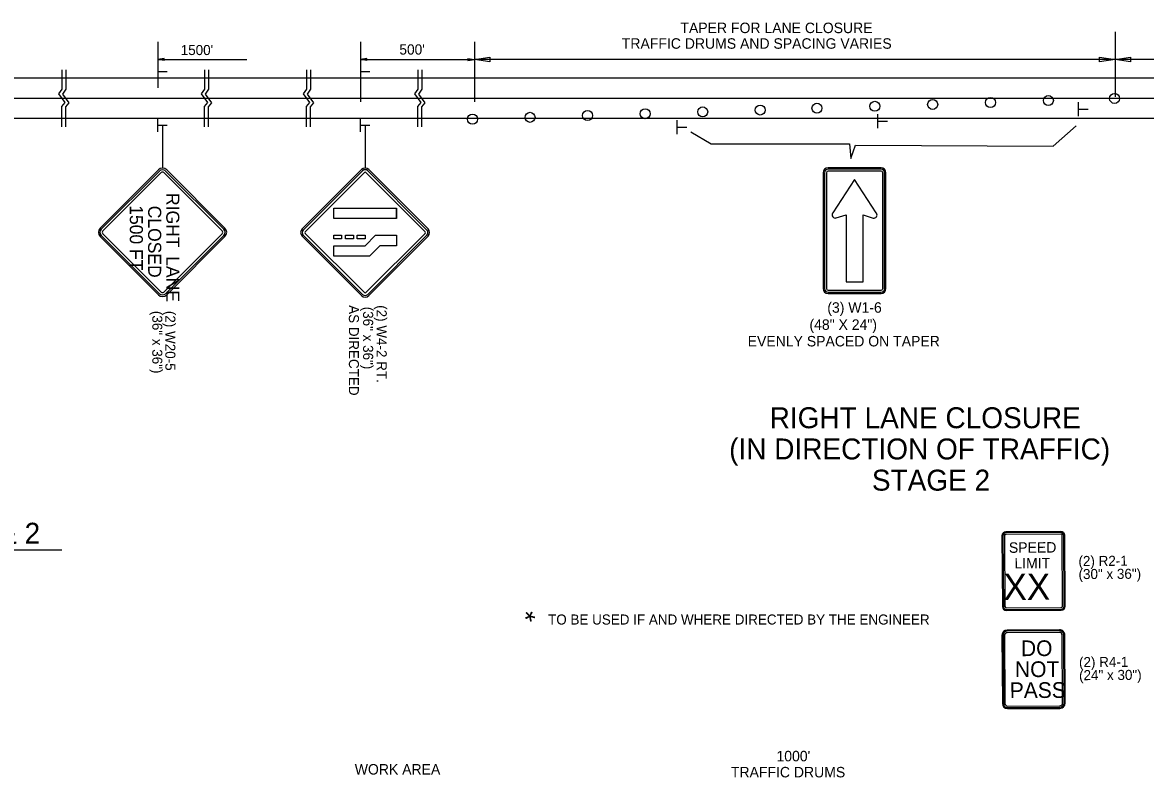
# Model space of a CAD drawing. Extents: x 1930579 to 1938745, y 596452 to 597559.
# Drawn here: x 1937136 to 1937779, y 597006 to 597439 of the extents above; entities that cross this region are included whole.
import ezdxf

# ---------------------------------------------------------------- set-up
doc = ezdxf.new("R2010")
doc.units = 0
for name, color, linetype in [('Default', 7, 'Continuous'), ('P_TC_Signs_Permanent', 7, 'Continuous'), ('P_TC_Signs_Temporary', 7, 'Continuous'), ('R_Annotation', 7, 'Continuous')]:
    doc.layers.add(name, color=color, linetype=linetype)

msp = doc.modelspace()

# ---------------------------------------------------------------- linework, layer by layer
at = {"layer": 'Default'}
for p, q in [((1937761.74, 597433.33), (1937761.74, 597396.03)), ((1937213.06, 597427.55), (1937213.06, 597401.26)), ((1937329.17, 597427.55), (1937329.17, 597393.08)), ((1937394.52, 597427.55), (1937394.52, 597393.08)), ((1937216.73, 597417.99), (1937213.06, 597417.44)), ((1937213.06, 597417.44), (1937264.16, 597417.44)), ((1937216.73, 597416.89), (1937213.06, 597417.44)), ((1937213.06, 597414.35), (1937213.06, 597406.69)), ((1937216.73, 597417.9), (1937213.67, 597417.44)), ((1937216.73, 597416.98), (1937213.67, 597417.44)), ((1937216.73, 597417.81), (1937214.3, 597417.44)), ((1937216.73, 597417.08), (1937214.3, 597417.44)), ((1937216.73, 597417.72), (1937214.91, 597417.44)), ((1937216.73, 597417.17), (1937214.91, 597417.44)), ((1937216.73, 597417.62), (1937215.54, 597417.44)), ((1937216.73, 597417.27), (1937215.54, 597417.44)), ((1937216.73, 597417.53), (1937216.15, 597417.44)), ((1937216.73, 597417.36), (1937216.15, 597417.44)), ((1937216.73, 597416.89), (1937216.73, 597417.99)), ((1937332.85, 597417.99), (1937329.17, 597417.44)), ((1937329.17, 597417.44), (1937394.52, 597417.44)), ((1937332.85, 597416.89), (1937329.17, 597417.44)), ((1937329.17, 597414.32), (1937329.17, 597406.66)), ((1937332.85, 597417.9), (1937329.79, 597417.44)), ((1937332.85, 597416.98), (1937329.79, 597417.44)), ((1937332.85, 597417.81), (1937330.42, 597417.44)), ((1937332.85, 597417.08), (1937330.42, 597417.44)), ((1937332.85, 597417.72), (1937331.03, 597417.44)), ((1937332.85, 597417.17), (1937331.03, 597417.44)), ((1937332.85, 597417.62), (1937331.65, 597417.44)), ((1937332.85, 597417.27), (1937331.65, 597417.44)), ((1937332.85, 597417.53), (1937332.27, 597417.44)), ((1937332.85, 597417.36), (1937332.27, 597417.44)), ((1937332.85, 597416.89), (1937332.85, 597417.99)), ((1937390.85, 597417.99), (1937394.52, 597417.44)), ((1937390.85, 597417.99), (1937390.85, 597416.89)), ((1937390.85, 597417.9), (1937393.91, 597417.44)), ((1937390.85, 597417.81), (1937393.28, 597417.44)), ((1937390.85, 597417.72), (1937392.67, 597417.44)), ((1937390.85, 597417.62), (1937392.04, 597417.44)), ((1937390.85, 597417.53), (1937391.43, 597417.44)), ((1937390.85, 597416.89), (1937394.52, 597417.44)), ((1937390.85, 597417.26), (1937392.04, 597417.44)), ((1937390.85, 597417.08), (1937393.28, 597417.44)), ((1937390.85, 597416.98), (1937393.91, 597417.44)), ((1937390.85, 597417.17), (1937392.67, 597417.44)), ((1937390.85, 597417.36), (1937391.43, 597417.44)), ((1937394.52, 597417.44), (1937403.39, 597418.77)), ((1937761.74, 597417.44), (1937394.52, 597417.44)), ((1937403.39, 597416.11), (1937394.52, 597417.44)), ((1937403.39, 597418.77), (1937403.39, 597416.11)), ((1937752.87, 597416.11), (1937752.87, 597418.77)), ((1937752.87, 597418.77), (1937761.74, 597417.44)), ((1937761.74, 597417.44), (1937752.87, 597416.11)), ((1937761.74, 597417.44), (1937770.61, 597418.77)), ((1938013.48, 597417.44), (1937761.74, 597417.44)), ((1937770.61, 597416.11), (1937761.74, 597417.44)), ((1937770.61, 597418.77), (1937770.61, 597416.11)), ((1937394.52, 597406.66), (1936726.79, 597406.66)), ((1937213.17, 597410.54), (1937218.4, 597410.54)), ((1937329.29, 597410.51), (1937334.52, 597410.51)), ((1938013.48, 597406.66), (1937394.52, 597406.66)), ((1938013.48, 597395.14), (1936726.79, 597395.14)), ((1937740.75, 597384.95), (1937740.75, 597392.93)), ((1937740.86, 597388.92), (1937746.31, 597388.92)), ((1937394.52, 597383.62), (1936726.79, 597383.62)), ((1937213.06, 597375.94), (1937213.06, 597383.6)), ((1937329.17, 597375.96), (1937329.17, 597383.62)), ((1938013.48, 597383.62), (1937394.52, 597383.62)), ((1937510.83, 597374.68), (1937510.83, 597382.66)), ((1937625.79, 597378.17), (1937625.79, 597386.15)), ((1937625.9, 597382.14), (1937631.35, 597382.14)), ((1937213.17, 597379.75), (1937218.4, 597379.75)), ((1937329.29, 597379.77), (1937334.52, 597379.77)), ((1937510.94, 597378.65), (1937516.39, 597378.65)), ((1937029.73, 597136.48), (1937158.05, 597136.48))]:
    msp.add_line(p, q, dxfattribs=at)
for points in [[(1937158, 597411.46), (1937158, 597400.51), (1937156.13, 597397.73), (1937159.78, 597392.74), (1937157.86, 597390.44), (1937157.86, 597378.82)], [(1937160.3, 597411.46), (1937160.3, 597400.41), (1937158.43, 597397.63), (1937162.08, 597392.65), (1937160.16, 597390.34), (1937160.16, 597378.82)], [(1937239.79, 597411.46), (1937239.79, 597400.51), (1937237.92, 597397.73), (1937241.56, 597392.74), (1937239.65, 597390.44), (1937239.64, 597378.82)], [(1937242.09, 597411.46), (1937242.09, 597400.41), (1937240.22, 597397.63), (1937243.86, 597392.65), (1937241.95, 597390.34), (1937241.94, 597378.82)], [(1937298.24, 597411.46), (1937298.24, 597400.51), (1937296.37, 597397.73), (1937300.01, 597392.74), (1937298.09, 597390.44), (1937298.09, 597378.82)], [(1937300.54, 597411.46), (1937300.54, 597400.41), (1937298.67, 597397.63), (1937302.31, 597392.65), (1937300.39, 597390.34), (1937300.39, 597378.82)], [(1937362.04, 597411.46), (1937362.04, 597400.51), (1937360.17, 597397.73), (1937363.81, 597392.74), (1937361.89, 597390.44), (1937361.89, 597378.82)], [(1937364.34, 597411.46), (1937364.34, 597400.41), (1937362.47, 597397.63), (1937366.11, 597392.65), (1937364.19, 597390.34), (1937364.19, 597378.82)]]:
    msp.add_lwpolyline(points, dxfattribs=at)
for centre in [(1937624.05, 597390.61), (1937657.2, 597391.71), (1937690.35, 597392.81), (1937723.51, 597393.91), (1937761.45, 597395.13), (1937426.43, 597384.29), (1937459.41, 597385.33), (1937492.4, 597386.38), (1937525.38, 597387.42), (1937558.36, 597388.47), (1937590.89, 597389.51), (1937393.45, 597383.25)]:
    msp.add_circle(centre, 2.87, dxfattribs=at)
at = {"layer": 'P_TC_Signs_Permanent'}
for p, q in [((1937627.62, 597355.36), (1937597.25, 597355.36)), ((1937295.84, 597320.38), (1937329.78, 597354.33)), ((1937594.43, 597352.55), (1937594.43, 597286.17)), ((1937595.18, 597352.55), (1937595.18, 597286.17)), ((1937596.31, 597352.55), (1937596.31, 597286.17)), ((1937627.62, 597354.61), (1937597.25, 597354.61)), ((1937627.62, 597353.49), (1937597.25, 597353.49)), ((1937628.56, 597286.17), (1937628.56, 597352.55)), ((1937629.68, 597286.17), (1937629.68, 597352.55)), ((1937630.43, 597286.17), (1937630.43, 597352.55)), ((1937349.9, 597326.3), (1937349.9, 597332.3)), ((1937329.78, 597282.2), (1937295.84, 597316.14)), ((1937367.96, 597316.14), (1937334.02, 597282.2)), ((1937597.25, 597285.24), (1937627.62, 597285.24)), ((1937597.25, 597284.11), (1937627.62, 597284.11)), ((1937597.25, 597283.36), (1937627.62, 597283.36)), ((1937696.94, 597144.56), (1937697.16, 597104.06)), ((1937697.5, 597144.56), (1937697.72, 597104.06)), ((1937698.44, 597144.57), (1937698.66, 597104.07)), ((1937730.68, 597146.99), (1937699.18, 597146.82)), ((1937730.68, 597146.43), (1937699.18, 597146.26)), ((1937730.69, 597145.49), (1937699.19, 597145.32)), ((1937731.66, 597104.25), (1937731.44, 597144.75)), ((1937732.6, 597104.25), (1937732.38, 597144.75)), ((1937733.16, 597104.26), (1937732.94, 597144.76)), ((1937699.41, 597103.32), (1937730.91, 597103.49)), ((1937699.42, 597102.38), (1937730.92, 597102.56)), ((1937699.42, 597101.82), (1937730.92, 597101.99)), ((1937696.93, 597087.56), (1937697.15, 597048.56)), ((1937697.53, 597087.57), (1937697.75, 597048.57)), ((1937698.43, 597087.57), (1937698.65, 597048.57)), ((1937729.92, 597090.74), (1937699.92, 597090.58)), ((1937729.92, 597090.14), (1937699.92, 597089.98)), ((1937729.93, 597089.24), (1937699.93, 597089.08)), ((1937731.65, 597048.75), (1937731.43, 597087.75)), ((1937732.55, 597048.76), (1937732.33, 597087.76)), ((1937733.15, 597048.76), (1937732.93, 597087.76)), ((1937700.16, 597047.08), (1937730.15, 597047.24)), ((1937700.16, 597046.18), (1937730.16, 597046.34)), ((1937700.16, 597045.58), (1937730.16, 597045.74))]:
    msp.add_line(p, q, dxfattribs=at)
for points in [[(1937330.42, 597353.69), (1937296.48, 597319.75)], [(1937297.54, 597318.69), (1937331.48, 597352.63)], [(1937332.33, 597352.63), (1937366.27, 597318.69)], [(1937367.33, 597319.75), (1937333.39, 597353.69)], [(1937334.02, 597354.33), (1937350.99, 597337.36), (1937367.96, 597320.38)], [(1937624.88, 597329.62), (1937612.43, 597348.61), (1937600.03, 597329.61)], [(1937601.8, 597326.66), (1937607.56, 597328.38), (1937607.56, 597290.11), (1937617.31, 597290.11), (1937617.31, 597328.38), (1937623.06, 597326.63)], [(1937296.48, 597316.78), (1937330.42, 597282.84)], [(1937331.48, 597283.9), (1937297.54, 597317.84)], [(1937366.27, 597317.84), (1937332.33, 597283.9)], [(1937333.39, 597282.84), (1937367.33, 597316.78)]]:
    msp.add_lwpolyline(points, dxfattribs=at)
for points in [[(1937313.9, 597326.3), (1937313.9, 597332.3), (1937349.9, 597332.3), (1937349.9, 597326.3)], [(1937313.9, 597314.66), (1937313.9, 597316.76), (1937318.4, 597316.76), (1937318.4, 597314.66)], [(1937313.9, 597304.76), (1937313.9, 597310.76), (1937331.9, 597310.76), (1937337.9, 597316.76), (1937349.9, 597316.76), (1937349.9, 597310.76), (1937340.39, 597310.76), (1937334.39, 597304.76)], [(1937320.65, 597314.66), (1937320.65, 597316.76), (1937325.15, 597316.76), (1937325.15, 597314.66)], [(1937327.4, 597314.66), (1937327.4, 597316.76), (1937331.9, 597316.76), (1937331.9, 597314.66)]]:
    msp.add_lwpolyline(points, close=True, dxfattribs=at)
for centre, radius, start, end in [((1937331.9, 597352.2), 3, 45, 135), ((1937597.25, 597352.55), 2.81, 90, 180), ((1937627.62, 597352.55), 2.81, 360, 90), ((1937331.9, 597352.2), 2.1, 45, 135), ((1937331.9, 597352.2), 0.6, 45, 135), ((1937597.25, 597352.55), 2.06, 90, 180), ((1937597.25, 597352.55), 0.938, 90, 180), ((1937627.62, 597352.55), 2.06, 360, 90), ((1937627.62, 597352.55), 0.938, 360, 90), ((1937601.31, 597328.36), 1.76, 146.59943, 285.96908), ((1937537.23, 597370.61), 75, 326.59943, 326.85697), ((1937623.55, 597328.36), 1.8, 254.03093, 33.47548), ((1937687.61, 597370.72), 75, 213.2286, 213.47548), ((1937297.96, 597318.26), 3, 135, 225), ((1937297.96, 597318.26), 2.1, 135, 225), ((1937297.96, 597318.26), 0.6, 135, 225), ((1937365.84, 597318.26), 0.6, 315, 45), ((1937365.84, 597318.26), 2.1, 315, 45), ((1937365.84, 597318.26), 3, 315, 45), ((1937597.25, 597286.17), 2.81, 180, 270), ((1937597.25, 597286.17), 2.06, 180, 270), ((1937597.25, 597286.17), 0.937, 180, 270), ((1937627.62, 597286.17), 2.81, 270, 360), ((1937627.62, 597286.17), 2.06, 270, 360), ((1937627.62, 597286.17), 0.938, 270, 360), ((1937331.9, 597284.32), 3, 225, 315), ((1937331.9, 597284.32), 2.1, 225, 315), ((1937331.9, 597284.32), 0.6, 225, 315), ((1937699.19, 597144.57), 2.25, 90.31197, 180.31197), ((1937699.19, 597144.57), 1.69, 90.31197, 180.31197), ((1937699.19, 597144.57), 0.75, 90.31197, 180.31197), ((1937730.69, 597144.74), 2.25, 0.31197, 90.31197), ((1937730.69, 597144.74), 1.69, 0.31197, 90.31197), ((1937730.69, 597144.74), 0.75, 0.31197, 90.31197), ((1937699.41, 597104.07), 2.25, 180.31197, 270.31197), ((1937699.41, 597104.07), 1.69, 180.31197, 270.31197), ((1937699.41, 597104.07), 0.75, 180.31197, 270.31197), ((1937730.91, 597104.24), 0.75, 270.31197, 0.31197), ((1937730.91, 597104.24), 2.25, 270.31197, 0.31197), ((1937730.91, 597104.24), 1.69, 270.31197, 0.31197), ((1937699.93, 597087.58), 3, 90.31197, 180.31197), ((1937699.93, 597087.58), 2.4, 90.31197, 180.31197), ((1937699.93, 597087.58), 1.5, 90.31197, 180.31197), ((1937729.93, 597087.74), 3, 0.31197, 90.31197), ((1937729.93, 597087.74), 2.4, 0.31197, 90.31197), ((1937729.93, 597087.74), 1.5, 0.31197, 90.31197), ((1937700.15, 597048.58), 3, 180.31197, 270.31197), ((1937700.15, 597048.58), 2.4, 180.31197, 270.31197), ((1937700.15, 597048.58), 1.5, 180.31197, 270.31197), ((1937730.15, 597048.74), 1.5, 270.31197, 0.31197), ((1937730.15, 597048.74), 3, 270.31197, 0.31197), ((1937730.15, 597048.74), 2.4, 270.31197, 0.31197)]:
    msp.add_arc(centre, radius, start, end, dxfattribs=at)
at = {"layer": 'P_TC_Signs_Temporary'}
for p, q in [((1937179.99, 597320.8), (1937213.4, 597354.22)), ((1937180.65, 597320.14), (1937214.06, 597353.55)), ((1937181.58, 597319.21), (1937214.99, 597352.62)), ((1937216.58, 597352.62), (1937249.99, 597319.21)), ((1937217.51, 597353.55), (1937250.92, 597320.14)), ((1937218.17, 597354.22), (1937251.58, 597320.8)), ((1937214.06, 597283.28), (1937180.65, 597316.69)), ((1937214.99, 597284.21), (1937181.58, 597317.62)), ((1937249.99, 597317.62), (1937216.58, 597284.21)), ((1937250.92, 597316.69), (1937217.51, 597283.28)), ((1937213.4, 597282.62), (1937179.99, 597316.03)), ((1937251.58, 597316.03), (1937218.17, 597282.62))]:
    msp.add_line(p, q, dxfattribs=at)
for centre, radius, start, end in [((1937215.79, 597351.83), 3.37, 45, 135), ((1937215.79, 597351.83), 2.44, 45, 135), ((1937215.79, 597351.83), 1.12, 45, 135), ((1937182.37, 597318.42), 3.37, 135, 225), ((1937182.37, 597318.42), 2.44, 135, 225), ((1937182.37, 597318.42), 1.13, 135, 225), ((1937249.2, 597318.42), 1.13, 315, 45), ((1937249.2, 597318.42), 2.44, 315, 45), ((1937249.2, 597318.42), 3.37, 315, 45), ((1937215.79, 597285.01), 1.12, 225, 315), ((1937215.79, 597285.01), 3.37, 225, 315), ((1937215.79, 597285.01), 2.44, 225, 315)]:
    msp.add_arc(centre, radius, start, end, dxfattribs=at)
at = {"layer": 'R_Annotation'}
for p, q in [((1937215.79, 597379.75), (1937215.79, 597355.22)), ((1937331.9, 597379.77), (1937331.9, 597355.2))]:
    msp.add_line(p, q, dxfattribs=at)
msp.add_lwpolyline([(1937518.5, 597376.04), (1937530.31, 597369.09), (1937609.52, 597369.09), (1937610.21, 597360.75), (1937612.99, 597368.39), (1937726.24, 597367.7), (1937739.44, 597379.52)], dxfattribs=at)

# ---------------------------------------------------------------- texts
at = {"layer": 'Default'}
for s, height, p in [('TAPER FOR LANE CLOSURE', 6, (1937512.63, 597432.54)), ("1500'", 5.76, (1937226.22, 597419.97)), ("500'", 5.875, (1937351.54, 597420.24)), ('TRAFFIC DRUMS AND SPACING VARIES ', 6, (1937479.03, 597423.59)), ('RIGHT LANE CLOSURE ', 12, (1937563.79, 597206.21)), ('(IN DIRECTION OF TRAFFIC)', 12, (1937540.55, 597188.33)), ('STAGE 2', 12, (1937622.37, 597170.46)), ('STAGES 1   & 2', 12, (1937029.73, 597140.05)), ("1000'", 6, (1937567.68, 597015.4)), ('WORK AREA', 6, (1937325.96, 597007.82)), ('TRAFFIC DRUMS ', 6, (1937541.56, 597006.2))]:
    msp.add_text(s, height=height, rotation=360, dxfattribs=at).set_placement(p)
at = {"layer": 'P_TC_Signs_Permanent'}
for s, height, rotation, p in [('SPEED', 6, 0.31197, (1937700.92, 597134.83)), ('LIMIT', 6, 0.31197, (1937704.06, 597125.85)), ('XX', 15, 0.31197, (1937697.84, 597107.81)), ('DO', 9, 0.31197, (1937707.83, 597075.62)), ('NOT', 9, 0.27162, (1937704.41, 597063.61)), ('PASS', 9, 0.31197, (1937701.42, 597051.59))]:
    msp.add_text(s, height=height, rotation=rotation, dxfattribs=at).set_placement(p)
at = {"layer": 'P_TC_Signs_Temporary'}
for s, p in [('RIGHT\u2002LANE', (1937217.91, 597340.94)), ('1500 FT', (1937197.04, 597333.94)), ('CLOSED', (1937207.54, 597333.67))]:
    msp.add_text(s, height=7.5, rotation=270, dxfattribs=at).set_placement(p)
at = {"layer": 'R_Annotation'}
for s, height, rotation, p in [('(3) W1-6', 6, 0.00754, (1937596.82, 597272.36)), ('(36" x 36")', 5.76, 270, (1937209.91, 597273.43)), ('(2) W20-5', 5.76, 270, (1937217.4, 597273.43)), ('AS DIRECTED ', 5.76, 270, (1937322.59, 597276.69)), ('(36" x 36")', 5.76, 270, (1937330.75, 597275.81)), ('(2) W4-2 RT.', 5.76, 270, (1937338.55, 597276.69)), ('(48" X 24")', 6, 0.00754, (1937586.59, 597262.56)), ('EVENLY SPACED ON TAPER', 6, 0.00754, (1937551.18, 597253.06)), ('(2) R2-1', 5.76, 0.31197, (1937740.78, 597127.27)), ('(30" x 36")', 5.76, 0.31197, (1937740.82, 597119.78)), ('*', 11.52, 45, (1937430.21, 597090.36)), ('TO BE USED IF AND WHERE DIRECTED BY THE ENGINEER', 5.76, 360, (1937436.77, 597093.75)), ('(2) R4-1', 5.76, 0.31197, (1937741.09, 597069.35)), ('(24" x 30")', 5.76, 0.31197, (1937741.13, 597061.86))]:
    msp.add_text(s, height=height, rotation=rotation, dxfattribs=at).set_placement(p)

doc.saveas('drawing.dxf')
